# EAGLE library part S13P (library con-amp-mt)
AMP MT CONNECTOR
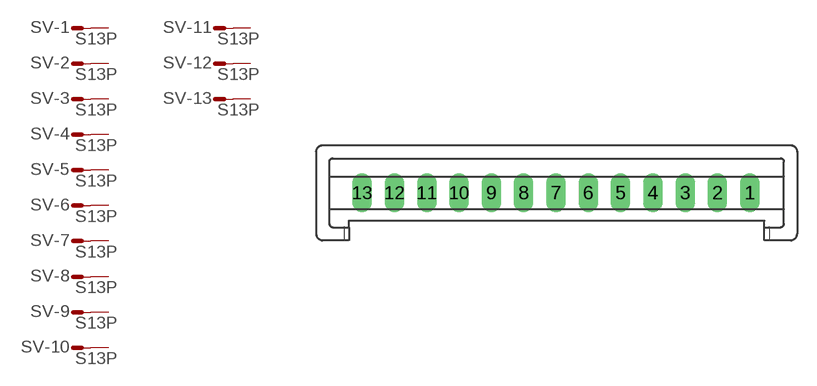
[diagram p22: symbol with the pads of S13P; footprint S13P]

Designator prefix SV; gates -1=M -2=M -3=M -4=M -5=M -6=M -7=M -8=M -9=M -10=M -11=M -12=M -13=M

## S13P (OC_FARNELL: unknown; OC_NEWARK: unknown)  [S13P]
1  -1:S  pas
2  -2:S  pas
3  -3:S  pas
4  -4:S  pas
5  -5:S  pas
6  -6:S  pas
7  -7:S  pas
8  -8:S  pas
9  -9:S  pas
10  -10:S  pas
11  -11:S  pas
12  -12:S  pas
13  -13:S  pas

## Footprint S13P (pad centres in mm)
AMP MT CONNECTOR
drill 1.016 long: 1 15,0; 2 12.5,0; 3 10,0; 4 7.5,0; 5 5,0; 6 2.5,0; 7 0,0; 8 -2.5,0; 9 -5,0; 10 -7.5,0; 11 -10,0; 12 -12.5,0; 13 -15,0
